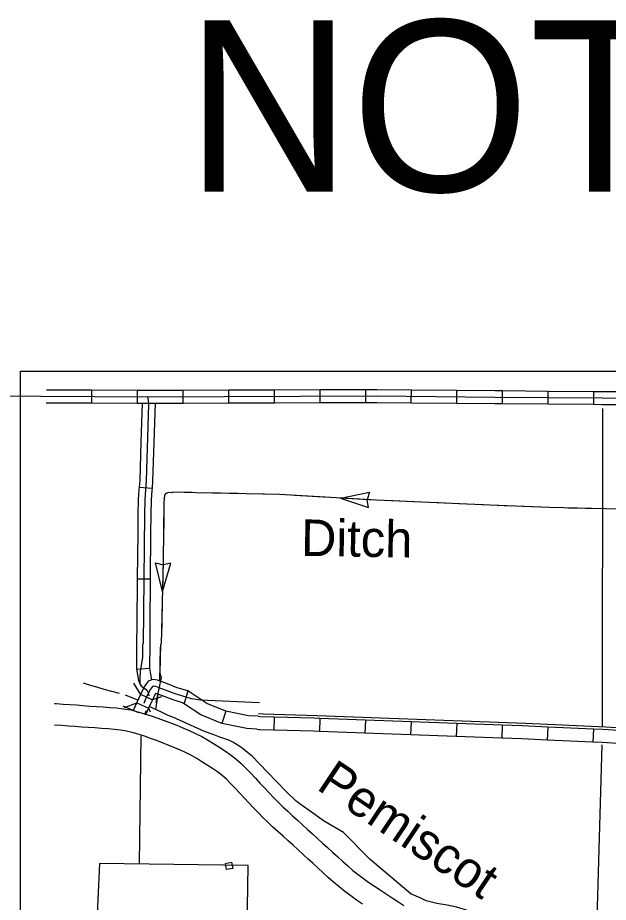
# Model space of a CAD drawing. Extents: x 1366406 to 1373462, y 376856 to 381998.
# Drawn here: x 1368990.1 to 1369100.9, y 380268.5 to 380434.5 of the extents above; entities that cross this region are included whole.
import ezdxf

# ---------------------------------------------------------------- set-up
doc = ezdxf.new("R2010")
doc.units = 0
for name, color, linetype in [('10', 7, 'Continuous'), ('32', 7, 'Continuous'), ('35', 7, 'Continuous'), ('38', 7, 'Continuous'), ('43', 7, 'Continuous'), ('45', 7, 'Continuous'), ('5', 7, 'Continuous'), ('56', 7, 'Continuous'), ('6', 7, 'Continuous'), ('Level 2', 7, 'Continuous'), ('R_No Plot', 7, 'Continuous')]:
    doc.layers.add(name, color=color, linetype=linetype)

msp = doc.modelspace()

# ---------------------------------------------------------------- linework, layer by layer
at = {"layer": '10'}
for points in [[(1368997.05, 380305.83), (1368997.43, 380305.8), (1368998.67, 380305.7), (1368999.91, 380305.62), (1369001.17, 380305.53), (1369002.42, 380305.43), (1369003.65, 380305.33), (1369004.89, 380305.25), (1369006.13, 380305.16), (1369007.38, 380305.08), (1369008.67, 380304.97), (1369009.99, 380304.82), (1369011.34, 380304.59), (1369012.66, 380304.27), (1369013.93, 380303.89), (1369015.17, 380303.49), (1369016.39, 380303.07), (1369017.58, 380302.63), (1369018.77, 380302.17), (1369019.94, 380301.71), (1369021.1, 380301.24), (1369022.29, 380300.75), (1369023.47, 380300.2), (1369024.63, 380299.61), (1369025.74, 380298.98), (1369026.82, 380298.32), (1369027.86, 380297.66), (1369028.9, 380296.98), (1369029.95, 380296.25), (1369031.01, 380295.45), (1369032.02, 380294.55), (1369032.95, 380293.63), (1369033.83, 380292.71), (1369034.69, 380291.79), (1369035.55, 380290.88), (1369036.4, 380289.97), (1369037.25, 380289.07), (1369038.12, 380288.17), (1369038.99, 380287.29), (1369039.86, 380286.42), (1369040.75, 380285.58), (1369041.67, 380284.74), (1369042.6, 380283.9), (1369043.55, 380283.04), (1369044.49, 380282.19), (1369045.42, 380281.33), (1369046.36, 380280.48), (1369047.3, 380279.62), (1369048.24, 380278.76), (1369049.18, 380277.9), (1369050.13, 380277.04), (1369051.08, 380276.17), (1369052.02, 380275.32), (1369052.98, 380274.5), (1369053.94, 380273.72), (1369054.94, 380272.98), (1369055.97, 380272.25), (1369057.03, 380271.54), (1369058.11, 380270.83), (1369059.21, 380270.11), (1369060.31, 380269.37), (1369061.42, 380268.64), (1369062.54, 380267.91)], [(1369054.78, 380268.16), (1369053.67, 380268.92), (1369052.56, 380269.7), (1369051.45, 380270.53), (1369050.38, 380271.4), (1369049.35, 380272.28), (1369048.36, 380273.17), (1369047.4, 380274.04), (1369046.45, 380274.91), (1369045.51, 380275.77), (1369044.57, 380276.63), (1369043.63, 380277.48), (1369042.69, 380278.34), (1369041.76, 380279.2), (1369040.82, 380280.05), (1369039.89, 380280.89), (1369038.95, 380281.74), (1369037.99, 380282.62), (1369037.05, 380283.51), (1369036.12, 380284.43), (1369035.22, 380285.34), (1369034.33, 380286.26), (1369033.45, 380287.19), (1369032.58, 380288.11), (1369031.73, 380289.03), (1369030.89, 380289.93), (1369030.06, 380290.79), (1369029.26, 380291.6), (1369028.44, 380292.31), (1369027.57, 380292.97), (1369026.64, 380293.62), (1369025.67, 380294.26), (1369024.68, 380294.88), (1369023.7, 380295.48), (1369022.71, 380296.04), (1369021.7, 380296.56), (1369020.66, 380297.04), (1369019.57, 380297.49), (1369018.44, 380297.95), (1369017.3, 380298.4), (1369016.16, 380298.84), (1369015.02, 380299.26), (1369013.88, 380299.66), (1369012.74, 380300.02), (1369011.61, 380300.35), (1369010.52, 380300.62), (1369009.42, 380300.81), (1369008.27, 380300.94), (1369007.08, 380301.04), (1369005.85, 380301.12), (1369004.61, 380301.21), (1369003.36, 380301.29), (1369002.1, 380301.39), (1369000.86, 380301.49), (1368999.63, 380301.58), (1368998.38, 380301.66), (1368997.12, 380301.76), (1368997.05, 380301.77)]]:
    msp.add_lwpolyline(points, dxfattribs=at)
at = {"layer": '32'}
for p, q in [((1369004.05, 380362.19), (1369004.06, 380364.62)), ((1369012.6, 380362.15), (1369012.61, 380364.58)), ((1369021.16, 380362.17), (1369021.16, 380364.6)), ((1369029.72, 380362.19), (1369029.71, 380364.62)), ((1369038.27, 380362.22), (1369038.26, 380364.65)), ((1369046.83, 380362.25), (1369046.82, 380364.68)), ((1369055.38, 380362.27), (1369055.37, 380364.7)), ((1369063.92, 380362.22), (1369063.94, 380364.65)), ((1369072.47, 380362.14), (1369072.49, 380364.57)), ((1369081.03, 380362.06), (1369081.04, 380364.49)), ((1369089.58, 380361.99), (1369089.6, 380364.42)), ((1369098.13, 380361.93), (1369098.15, 380364.36)), ((1369013.18, 380307.53), (1369015.39, 380306.52)), ((1369022.06, 380308.15), (1369021.37, 380305.82)), ((1369012.45, 380305.93), (1369014.66, 380304.92)), ((1369029.13, 380304.38), (1369028.42, 380302.05)), ((1369038.22, 380303.25), (1369038.16, 380300.82)), ((1369046.78, 380302.99), (1369046.69, 380300.57)), ((1369055.33, 380302.68), (1369055.24, 380300.25)), ((1369063.88, 380302.36), (1369063.79, 380299.93)), ((1369072.43, 380302.04), (1369072.34, 380299.61)), ((1369080.98, 380301.73), (1369080.89, 380299.3)), ((1369089.53, 380301.37), (1369089.42, 380298.94)), ((1369098.08, 380300.99), (1369097.97, 380298.56))]:
    msp.add_line(p, q, dxfattribs=at)
for points in [[(1368944.66, 380365.32), (1368945.27, 380364.79), (1368945.98, 380364.3), (1368947.17, 380363.76), (1368948.17, 380363.56), (1368949.47, 380363.57), (1368950.6, 380363.56), (1368977.56, 380363.5), (1368994.49, 380363.45), (1369014.52, 380363.36), (1369057.49, 380363.5), (1369079.6, 380363.29), (1369099.69, 380363.13), (1369120.87, 380363.07), (1369134.89, 380362.95), (1369142.96, 380362.92), (1369155.95, 380362.94), (1369165.49, 380362.98), (1369174.24, 380363.07), (1369180.67, 380363.1), (1369185.83, 380363.06)], [(1368995.51, 380364.66), (1369004.06, 380364.62)], [(1369004.06, 380364.62), (1369012.61, 380364.58)], [(1369012.61, 380364.58), (1369014.52, 380364.58), (1369021.16, 380364.6)], [(1369021.16, 380364.6), (1369029.71, 380364.62)], [(1369029.71, 380364.62), (1369038.26, 380364.65)], [(1369038.26, 380364.65), (1369046.82, 380364.68)], [(1369046.82, 380364.68), (1369055.37, 380364.7)], [(1369055.37, 380364.7), (1369057.49, 380364.71), (1369063.94, 380364.65)], [(1369063.94, 380364.65), (1369072.49, 380364.57)], [(1369072.49, 380364.57), (1369079.61, 380364.5), (1369081.04, 380364.49)], [(1369081.04, 380364.49), (1369089.6, 380364.42)], [(1369089.6, 380364.42), (1369098.15, 380364.36)], [(1369098.15, 380364.36), (1369099.7, 380364.35), (1369106.7, 380364.33)], [(1368995.49, 380362.23), (1369004.05, 380362.19)], [(1369004.05, 380362.19), (1369012.6, 380362.15)], [(1369012.6, 380362.15), (1369014.52, 380362.15), (1369021.16, 380362.17)], [(1369021.16, 380362.17), (1369029.72, 380362.19)], [(1369029.72, 380362.19), (1369038.27, 380362.22)], [(1369038.27, 380362.22), (1369046.83, 380362.25)], [(1369046.83, 380362.25), (1369055.38, 380362.27)], [(1369055.38, 380362.27), (1369057.49, 380362.28), (1369063.92, 380362.22)], [(1369063.92, 380362.22), (1369072.47, 380362.14)], [(1369072.47, 380362.14), (1369079.59, 380362.07), (1369081.03, 380362.06)], [(1369081.03, 380362.06), (1369089.58, 380361.99)], [(1369089.58, 380361.99), (1369098.13, 380361.93)], [(1369098.13, 380361.93), (1369099.69, 380361.92), (1369106.69, 380361.9)], [(1369022.06, 380308.15), (1369020.04, 380308.77), (1369018.19, 380309.47), (1369016.36, 380310.15), (1369015.47, 380310.31), (1369014.62, 380309.98), (1369013.97, 380309.13), (1369013.43, 380308.05), (1369011.8, 380304.47)], [(1369035.45, 380305.93), (1369024.4, 380306.45), (1369022.72, 380306.69), (1369021.71, 380306.98), (1369019.65, 380307.62), (1369016.68, 380308.74), (1369016.04, 380308.97), (1369015.59, 380309.05), (1369015.38, 380308.97), (1369015, 380308.49), (1369014.53, 380307.53), (1369014.04, 380306.46), (1369013.8, 380305.78)], [(1369021.01, 380305.93), (1369019.26, 380306.47), (1369016.25, 380307.6), (1369015.97, 380307.7), (1369014.66, 380304.92), (1369014.17, 380303.82)], [(1369029.13, 380304.38), (1369025.59, 380305.81), (1369022.06, 380308.15)], [(1369028.42, 380302.05), (1369024.45, 380303.65), (1369021.01, 380305.93)], [(1369014.17, 380304.44), (1369014.13, 380304.36), (1369013.89, 380303.68)], [(1369035.24, 380303.41), (1369033.42, 380303.51), (1369029.13, 380304.38)], [(1369252.4, 380293.26), (1369251.01, 380293.38), (1369242.85, 380293.7), (1369229.28, 380294.44), (1369185.88, 380296.21), (1369163.73, 380297.31), (1369151.6, 380298.16), (1369120.91, 380300.08), (1369100.42, 380301.39), (1369085.32, 380302.07), (1369046.26, 380303.51), (1369036.14, 380303.8), (1369035.29, 380303.84)], [(1369034.96, 380300.99), (1369033.11, 380301.09), (1369028.42, 380302.05)], [(1369038.22, 380303.25), (1369035.53, 380303.32), (1369035.23, 380303.34)], [(1369046.78, 380302.99), (1369045.66, 380303.04), (1369038.22, 380303.25)], [(1369055.33, 380302.68), (1369046.78, 380302.99)], [(1369063.88, 380302.36), (1369055.33, 380302.68)], [(1369072.43, 380302.04), (1369063.88, 380302.36)], [(1369080.98, 380301.73), (1369072.43, 380302.04)], [(1369038.16, 380300.82), (1369035.44, 380300.89), (1369034.95, 380300.92)], [(1369046.69, 380300.57), (1369045.58, 380300.61), (1369038.16, 380300.82)], [(1369055.24, 380300.25), (1369046.69, 380300.57)], [(1369089.53, 380301.37), (1369084.72, 380301.59), (1369080.98, 380301.73)], [(1369098.08, 380300.99), (1369089.53, 380301.37)], [(1369106.64, 380300.47), (1369099.84, 380300.91), (1369098.08, 380300.99)], [(1369063.79, 380299.93), (1369055.24, 380300.25)], [(1369072.34, 380299.61), (1369063.79, 380299.93)], [(1369080.89, 380299.3), (1369072.34, 380299.61)], [(1369089.42, 380298.94), (1369084.62, 380299.16), (1369080.89, 380299.3)], [(1369097.97, 380298.56), (1369089.42, 380298.94)], [(1369106.48, 380298.05), (1369099.71, 380298.48), (1369097.97, 380298.56)]]:
    msp.add_lwpolyline(points, dxfattribs=at)
at = {"layer": '35'}
for points in [[(1369032.3, 380297.34), (1369031.99, 380297.58), (1369030.44, 380298.56), (1369029.69, 380298.94), (1369028.01, 380299.5), (1369026.77, 380299.97), (1369025.13, 380300.58), (1369019.24, 380303.23), (1369018.36, 380303.53), (1369017.07, 380304.15), (1369014.8, 380305.23)], [(1369063.92, 380270.04), (1369056.21, 380276.55), (1369051.23, 380281.59), (1369047.46, 380283.82), (1369045.82, 380284.99), (1369043.7, 380286.51), (1369042.36, 380287.47), (1369040.51, 380289.21), (1369036.9, 380293), (1369034.12, 380295.92), (1369032.3, 380297.34)], [(1369120.37, 380261.48), (1369117.29, 380260.83), (1369115, 380260.53), (1369111.83, 380259.89), (1369106.55, 380259.98), (1369097.06, 380260.2), (1369087.91, 380261.63), (1369085.17, 380262.04), (1369081.99, 380263.08), (1369078.68, 380264.7), (1369077.51, 380265.4), (1369076.42, 380266.1), (1369075.48, 380266.6), (1369074.11, 380267.1), (1369072.37, 380267.62), (1369070.66, 380267.97), (1369068.68, 380268.28), (1369066.69, 380268.81), (1369065.61, 380269.32), (1369064.11, 380269.97), (1369063.92, 380270.04)]]:
    msp.add_lwpolyline(points, dxfattribs=at)
at = {"layer": '38'}
for points in [[(1369013.18, 380307.53), (1369011.92, 380309.64)], [(1369017.12, 380307.07), (1369015.39, 380306.51)], [(1369010.17, 380305.08), (1369012.45, 380305.93)], [(1369014.66, 380304.92), (1369014.95, 380304.22)]]:
    msp.add_lwpolyline(points, dxfattribs=at)
at = {"layer": '43'}
for p, q in [((1369050.65, 380344.33), (1369056.09, 380345.45)), ((1369056.09, 380345.45), (1369055.63, 380344.05)), ((1369050.65, 380344.33), (1369055.92, 380342.58)), ((1369055.92, 380342.58), (1369055.62, 380344.03)), ((1369017.27, 380326.81), (1369015.96, 380332.21)), ((1369015.96, 380332.21), (1369017.38, 380331.79)), ((1369017.27, 380326.81), (1369018.84, 380332.14)), ((1369018.84, 380332.14), (1369017.4, 380331.79))]:
    msp.add_line(p, q, dxfattribs=at)
for points in [[(1369019.03, 380345.35), (1369018.37, 380345.38), (1369017.86, 380345.16), (1369017.63, 380344.87), (1369017.59, 380344.2), (1369017.54, 380343.47), (1369017.41, 380332.62), (1369017.03, 380316.91)], [(1369022.87, 380345.36), (1369019.15, 380345.43), (1369019.03, 380345.35), (1369018.37, 380345.38), (1369017.86, 380345.16), (1369017.63, 380344.87), (1369017.59, 380344.2), (1369017.57, 380343.91)], [(1369199.06, 380336.99), (1369185.55, 380337.68), (1369170.56, 380338.94), (1369158.41, 380339.78), (1369142.58, 380340.92), (1369120.88, 380341.72), (1369113.65, 380341.9), (1369102.97, 380342.24), (1369089.81, 380342.55), (1369078.65, 380343.02), (1369057.37, 380343.94), (1369039.23, 380345), (1369023.55, 380345.34), (1369019.15, 380345.43)], [(1369031.42, 380345.17), (1369025.01, 380345.31)], [(1369039.97, 380344.95), (1369039.23, 380345), (1369033.56, 380345.12)], [(1369045.31, 380344.64), (1369042.11, 380344.83)], [(1369048.51, 380344.46), (1369045.31, 380344.64)], [(1369057.05, 380343.96), (1369050.65, 380344.33)], [(1369065.6, 380343.58), (1369059.19, 380343.86)], [(1369074.14, 380343.22), (1369067.73, 380343.49)], [(1369082.69, 380342.85), (1369078.65, 380343.02), (1369076.28, 380343.12)], [(1369091.23, 380342.52), (1369089.81, 380342.55), (1369084.82, 380342.76)], [(1369096.58, 380342.39), (1369093.37, 380342.47)], [(1369099.79, 380342.32), (1369096.58, 380342.39)], [(1369017.52, 380341.77), (1369017.45, 380335.36)], [(1369017.42, 380333.22), (1369017.41, 380332.62), (1369017.27, 380326.81)], [(1369017.22, 380324.67), (1369017.14, 380321.46)], [(1369017.14, 380321.46), (1369017.07, 380318.26)], [(1369016.9, 380316.91), (1369016.76, 380311.51), (1369017, 380310.71), (1369016.91, 380310.04), (1369016.74, 380309.15), (1369016.06, 380306)], [(1369016.87, 380316.4), (1369016.71, 380310.02)], [(1369002.38, 380309.65), (1369003.75, 380309.25), (1369004.89, 380308.92), (1369006.3, 380308.51), (1369009.16, 380307.72)], [(1369010.31, 380307.42), (1369012.61, 380306.47)], [(1369016.39, 380307.55), (1369015.99, 380304.66)], [(1369012.86, 380304.07), (1369009.89, 380305.29)]]:
    msp.add_lwpolyline(points, dxfattribs=at)
at = {"layer": '45'}
for p, q in [((1369012.9, 380346.38), (1369015.33, 380346.18)), ((1369012.55, 380329.19), (1369014.98, 380329.17)), ((1369012.42, 380312.27), (1369014.85, 380312.46))]:
    msp.add_line(p, q, dxfattribs=at)
for points in [[(1369013.46, 380362.15), (1369013.23, 380354.86)], [(1369014.48, 380363.36), (1369014.61, 380362.68), (1369014.67, 380361.93), (1369014.22, 380347.59), (1369014.08, 380345.91), (1369013.96, 380343.98), (1369013.88, 380341.26), (1369013.64, 380317)], [(1369015.89, 380362.15), (1369015.66, 380354.79)], [(1369013.23, 380354.86), (1369013.01, 380347.65), (1369012.9, 380346.38)], [(1369015.66, 380354.79), (1369015.43, 380347.52), (1369015.33, 380346.18)], [(1369012.9, 380346.38), (1369012.87, 380345.99), (1369012.75, 380344.04), (1369012.67, 380341.28), (1369012.63, 380337.74)], [(1369015.33, 380346.18), (1369015.3, 380345.82), (1369015.18, 380343.93), (1369015.1, 380341.23), (1369015.06, 380337.72)], [(1369012.63, 380337.74), (1369012.55, 380329.19)], [(1369015.06, 380337.72), (1369014.98, 380329.17)], [(1369012.55, 380329.19), (1369012.46, 380320.64)], [(1369014.98, 380329.17), (1369014.89, 380320.61)], [(1369012.46, 380320.64), (1369012.43, 380317.03)], [(1369014.89, 380320.61), (1369014.88, 380316.97)], [(1369012.43, 380317.03), (1369012.38, 380312.46), (1369012.42, 380312.27)], [(1369013.53, 380317), (1369013.51, 380314.45), (1369013.09, 380311.86), (1369013.04, 380310.53), (1369013.05, 380310.03), (1369013.05, 380309.59), (1369013.15, 380309.3), (1369013.37, 380309.05), (1369014.2, 380308.45), (1369014.42, 380308.19), (1369014.58, 380307.79), (1369014.72, 380307.26)], [(1369014.88, 380316.97), (1369014.85, 380312.46)], [(1369012.42, 380312.27), (1369012.76, 380310.1), (1369013.16, 380309.23), (1369013.76, 380308.71)], [(1369014.85, 380312.46), (1369015.21, 380310.21)]]:
    msp.add_lwpolyline(points, dxfattribs=at)
at = {"layer": '5'}
for points in [[(1369099.77, 380361.12), (1369099.68, 380301.38)], [(1369012.97, 380275.7), (1369013.26, 380299.72)], [(1369099.62, 380298.03), (1369098.66, 380263.21)]]:
    msp.add_lwpolyline(points, dxfattribs=at)
at = {"layer": '56'}
msp.add_lwpolyline([(1369029.3, 380274.64), (1369029.07, 380275.79), (1369030.22, 380276.02), (1369030.45, 380274.87)], close=True, dxfattribs=at)
at = {"layer": '6'}
msp.add_lwpolyline([(1369033.3, 380255.77), (1369033, 380255.8), (1369033.36, 380275.42), (1369005.47, 380275.8), (1369004.68, 380258.35), (1369003.7, 380258.34), (1369003.52, 380251.52), (1369003.27, 380222.91), (1369003.06, 380221.93), (1369002.53, 380221.49), (1368998.4, 380216.78), (1368997.57, 380216.33), (1368996.39, 380216.47)], dxfattribs=at)
at = {"layer": 'R_No Plot'}
for p, q in [((1368990.63, 379480.59), (1368990.63, 380368.17)), ((1368990.63, 380368.17), (1369713.09, 380368.17))]:
    msp.add_line(p, q, dxfattribs=at)

# ---------------------------------------------------------------- texts
at = {"layer": '35'}
msp.add_text('Pemiscot', height=6.843, rotation=326.2109, dxfattribs=at).set_placement((1369045.94, 380289.85))
at = {"layer": '43'}
msp.add_text('Ditch', height=6.843, rotation=359.0862, dxfattribs=at).set_placement((1369043.22, 380333.51))
at = {"layer": 'Level 2'}
msp.add_text('NOT TO SCALE', height=32.1288, dxfattribs=at).set_placement((1369021.66, 380401.85))

doc.saveas('drawing.dxf')
